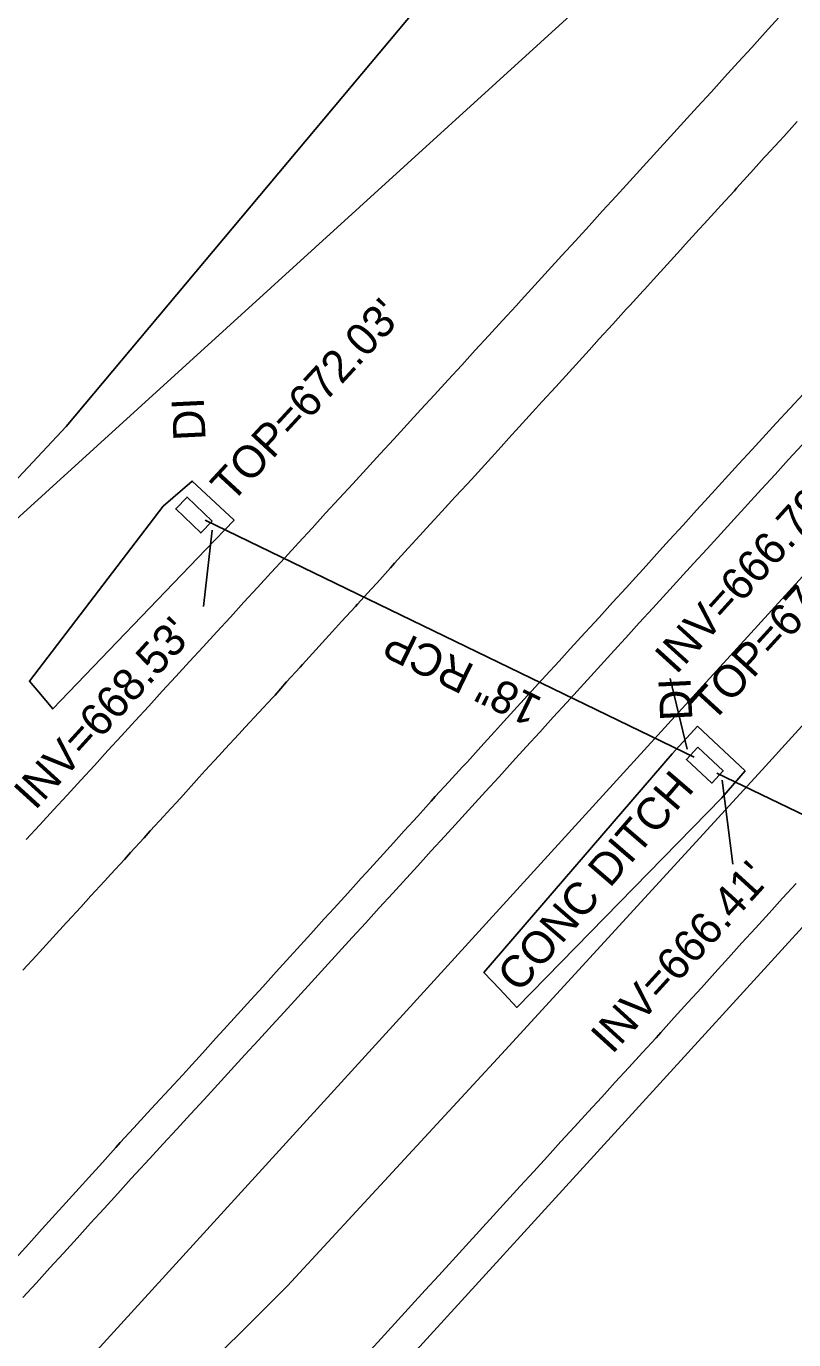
# Model space of a CAD drawing. Extents: x 1806071 to 1809844, y 912722 to 917035.
# Drawn here: x 1807955 to 1808050.3, y 914800.2 to 914963.4 of the extents above; entities that cross this region are included whole.
import ezdxf

# ---------------------------------------------------------------- set-up
doc = ezdxf.new("R2010")
doc.units = 0
for name, color, linetype in [('Exist Guardrail Cable Guide Rail', 7, 'Continuous'), ('Exist Horizontal Alignment', 7, 'Continuous'), ('Exist Roads EOP', 7, 'Continuous'), ('Exist Roads EOT', 7, 'Continuous'), ('Exist Structure Minor Drop Inlet', 7, 'Continuous'), ('Exist Structure Minor Drop Inlet Text', 7, 'Continuous'), ('Exist Structure Minor Drop Inlet Top Elevation', 7, 'Continuous'), ('Exist Structure Minor Paved Ditch or Gutter', 7, 'Continuous'), ('Exist Structure Minor Paved Ditch or Gutter Text', 7, 'Continuous'), ('Exist Structure Minor Pipes RCP 18 Inch', 7, 'Continuous'), ('Exist Structure Minor Pipes RCP 18 Inch Invert', 7, 'Continuous'), ('Exist Structure Minor Pipes RCP 18 Inch Text', 7, 'Continuous'), ('Exist Vegetation Hedge Row', 7, 'Continuous'), ('Exist Vegetation Woods Line', 7, 'Continuous')]:
    doc.layers.add(name, color=color, linetype=linetype)

msp = doc.modelspace()

# ---------------------------------------------------------------- linework, layer by layer
at = {"layer": 'Exist Guardrail Cable Guide Rail'}
msp.add_lwpolyline([(1807974.04, 914793.5), (1807987.44, 914806.88), (1808014.49, 914836.2), (1808046.81, 914871.43), (1808079.07, 914907.03), (1808115.43, 914946.85), (1808153.1, 914988.37), (1808190.68, 915029.49), (1808228.19, 915070.67), (1808264.68, 915110.73), (1808292.14, 915140.7), (1808316.64, 915167.2)], dxfattribs=at)
at = {"layer": 'Exist Horizontal Alignment'}
msp.add_line((1806073.69, 912724.84), (1809374.2, 916346.52), dxfattribs=at)
at = {"layer": 'Exist Roads EOP'}
for points in [[(1808048.45, 914964.45), (1808046.77, 914962.6), (1808045.08, 914960.75), (1808043.4, 914958.91), (1808041.72, 914957.06), (1808040.03, 914955.21), (1808038.35, 914953.36), (1808036.66, 914951.52), (1808034.98, 914949.67), (1808033.3, 914947.82), (1808031.61, 914945.97), (1808029.93, 914944.13), (1808028.24, 914942.28), (1808026.56, 914940.43), (1808024.88, 914938.58), (1808023.19, 914936.73), (1808021.51, 914934.89), (1808019.82, 914933.04), (1808018.14, 914931.19), (1808016.46, 914929.34), (1808015.83, 914928.65), (1808014.14, 914926.81), (1808012.45, 914924.97), (1808010.76, 914923.13), (1808009.07, 914921.28), (1808007.38, 914919.44), (1808005.69, 914917.6), (1808004, 914915.76), (1808002.31, 914913.91), (1808000.62, 914912.07), (1807998.93, 914910.23), (1807997.24, 914908.38), (1807995.55, 914906.54), (1807993.86, 914904.7), (1807992.17, 914902.86), (1807990.48, 914901.01), (1807988.79, 914899.17), (1807987.1, 914897.33), (1807985.41, 914895.49), (1807983.72, 914893.64), (1807982.03, 914891.8), (1807980.34, 914889.96), (1807978.65, 914888.12), (1807976.96, 914886.27), (1807975.27, 914884.43), (1807973.58, 914882.59), (1807971.89, 914880.75), (1807970.2, 914878.9), (1807968.52, 914877.06), (1807966.83, 914875.22), (1807965.14, 914873.38), (1807963.45, 914871.53), (1807961.76, 914869.69), (1807960.07, 914867.85), (1807958.38, 914866.01), (1807956.69, 914864.16), (1807955, 914862.32)], [(1807954.57, 914805.4), (1807956.26, 914807.25), (1807957.94, 914809.09), (1807959.62, 914810.94), (1807961.31, 914812.79), (1807962.99, 914814.64), (1807964.68, 914816.49), (1807966.36, 914818.34), (1807968.04, 914820.18), (1807968.62, 914820.82), (1807970.31, 914822.66), (1807972, 914824.51), (1807973.69, 914826.35), (1807975.38, 914828.19), (1807977.07, 914830.03), (1807978.77, 914831.87), (1807980.46, 914833.72), (1807982.15, 914835.56), (1807983.84, 914837.4), (1807985.53, 914839.24), (1807987.04, 914840.89), (1807988.72, 914842.74), (1807990.41, 914844.59), (1807992.09, 914846.43), (1807993.78, 914848.28), (1807995.46, 914850.13), (1807997.15, 914851.98), (1807998.83, 914853.82), (1808000.52, 914855.67), (1808002.2, 914857.52), (1808003.6, 914859.05), (1808005.28, 914860.9), (1808006.97, 914862.74), (1808008.65, 914864.59), (1808010.34, 914866.44), (1808012.02, 914868.29), (1808013.71, 914870.13), (1808015.39, 914871.98), (1808017.07, 914873.83), (1808018.76, 914875.68), (1808020.44, 914877.52), (1808022.13, 914879.37), (1808023.81, 914881.22), (1808025.5, 914883.06), (1808027.18, 914884.91), (1808028.87, 914886.76), (1808029.43, 914887.38), (1808031.12, 914889.23), (1808032.8, 914891.07), (1808034.49, 914892.92), (1808036.17, 914894.76), (1808037.86, 914896.61), (1808039.55, 914898.46), (1808041.23, 914900.3), (1808042.92, 914902.15), (1808044.6, 914903.99), (1808046.29, 914905.84), (1808047.98, 914907.69), (1808049.66, 914909.53), (1808051.35, 914911.38)], [(1808050.59, 914856.87), (1808048.91, 914855.02), (1808047.23, 914853.17), (1808045.55, 914851.32), (1808043.87, 914849.47), (1808042.19, 914847.61), (1808040.51, 914845.76), (1808038.83, 914843.91), (1808037.15, 914842.06), (1808035.47, 914840.21), (1808033.79, 914838.36), (1808033.2, 914837.7), (1808031.51, 914835.85), (1808029.82, 914834.01), (1808028.14, 914832.16), (1808026.45, 914830.31), (1808024.77, 914828.47), (1808023.08, 914826.62), (1808021.39, 914824.78), (1808019.71, 914822.93), (1808018.02, 914821.08), (1808016.34, 914819.24), (1808014.65, 914817.39), (1808012.96, 914815.55), (1808011.28, 914813.7), (1808009.59, 914811.85), (1808007.91, 914810.01), (1808006.22, 914808.16), (1808004.53, 914806.32), (1808002.85, 914804.47), (1808001.16, 914802.62), (1807999.48, 914800.78), (1807997.79, 914798.93)]]:
    msp.add_lwpolyline(points, dxfattribs=at)
at = {"layer": 'Exist Roads EOT'}
msp.add_line((1807617.6, 914375.74), (1808224.93, 915041.78), dxfattribs=at)
for points in [[(1807954.57, 914846.08), (1807956.26, 914847.93), (1807956.62, 914848.32), (1807958.31, 914850.16), (1807960.01, 914852), (1807960.08, 914852.08), (1807961.76, 914853.93), (1807963.02, 914855.31), (1807964.71, 914857.15), (1807965.48, 914858), (1807967.18, 914859.84), (1807967.96, 914860.69), (1807969.63, 914862.55), (1807970.4, 914863.39), (1807972.09, 914865.23), (1807972.46, 914865.63), (1807974.14, 914867.48), (1807974.8, 914868.2), (1807976.47, 914870.06), (1807977.22, 914870.89), (1807978.91, 914872.74), (1807979.68, 914873.59), (1807981.38, 914875.42), (1807982.17, 914876.28), (1807983.87, 914878.11), (1807985.58, 914879.94), (1807985.89, 914880.28), (1807987.32, 914881.91), (1807989, 914883.76), (1807989.28, 914884.07), (1807990.97, 914885.91), (1807991.73, 914886.75), (1807993.41, 914888.6), (1807994.16, 914889.43), (1807995.86, 914891.26), (1807996.13, 914891.56), (1807997.81, 914893.42), (1807998.55, 914894.24), (1808000.22, 914896.1), (1808000.73, 914896.68), (1808002.43, 914898.52), (1808003.43, 914899.61), (1808005.14, 914901.51), (1808006.58, 914903.08), (1808008.27, 914904.91), (1808009.08, 914905.79), (1808010.27, 914907.05), (1808011.94, 914908.9), (1808012.75, 914909.8), (1808013.97, 914911.14), (1808014.94, 914912.21), (1808016.61, 914914.06), (1808017.84, 914915.42), (1808019.05, 914916.75), (1808020.74, 914918.59), (1808022.01, 914919.96), (1808023.22, 914921.3), (1808024.9, 914923.15), (1808026.15, 914924.52), (1808027.83, 914926.37), (1808029.51, 914928.21), (1808029.93, 914928.67), (1808031.62, 914930.51), (1808031.77, 914930.68), (1808032.88, 914931.9), (1808034.57, 914933.77), (1808036.25, 914935.61), (1808036.87, 914936.29), (1808038.54, 914938.15), (1808039.16, 914938.84), (1808040.86, 914940.68), (1808041.24, 914941.09), (1808042.93, 914942.94), (1808043.21, 914943.25), (1808044.89, 914945.11), (1808044.98, 914945.21), (1808046.64, 914947.08), (1808046.82, 914947.28), (1808048.52, 914949.11), (1808049.05, 914949.69), (1808050.72, 914951.55)], [(1807953.64, 914810.24), (1807955.32, 914812.1), (1807956.99, 914813.96), (1807958.21, 914815.31), (1807959.89, 914817.16), (1807961.57, 914819), (1807962.78, 914820.34), (1807964.45, 914822.19), (1807966.12, 914824.05), (1807966.67, 914824.66), (1807968.36, 914826.5), (1807970.06, 914828.34), (1807971.05, 914829.42), (1807972.74, 914831.26), (1807974.43, 914833.1), (1807975.19, 914833.93), (1807976.87, 914835.78), (1807978.55, 914837.63), (1807979.54, 914838.72), (1807981.22, 914840.57), (1807982.9, 914842.42), (1807984.37, 914844.03), (1807986.04, 914845.88), (1807987.72, 914847.73), (1807988.64, 914848.75), (1807990.32, 914850.6), (1807992, 914852.45), (1807993.23, 914853.81), (1807994.91, 914855.66), (1807996.6, 914857.51), (1807997.25, 914858.23), (1807998.93, 914860.08), (1808000.61, 914861.93), (1808001.93, 914863.39), (1808003.6, 914865.24), (1808005.28, 914867.1), (1808005.79, 914867.66), (1808007.48, 914869.5), (1808009.17, 914871.34), (1808009.77, 914871.98), (1808011.45, 914873.84), (1808013.12, 914875.69), (1808013.87, 914876.52), (1808015.55, 914878.37), (1808017.23, 914880.22), (1808017.77, 914880.82), (1808019.46, 914882.66), (1808021.15, 914884.5), (1808022.16, 914885.61), (1808023.86, 914887.45), (1808025.55, 914889.3), (1808026.12, 914889.92), (1808027.81, 914891.76), (1808029.5, 914893.6), (1808030.29, 914894.47), (1808031.96, 914896.32), (1808033.64, 914898.18), (1808034.87, 914899.55), (1808036.55, 914901.4), (1808038.23, 914903.25), (1808039.25, 914904.38), (1808040.94, 914906.22), (1808042.63, 914908.06), (1808043.45, 914908.96), (1808045.14, 914910.8), (1808046.83, 914912.65), (1808048.12, 914914.05), (1808049.82, 914915.89), (1808051.52, 914917.72)], [(1807953.64, 914810.24), (1807955.32, 914812.1), (1807956.99, 914813.96), (1807958.21, 914815.31), (1807959.89, 914817.16), (1807961.57, 914819), (1807962.78, 914820.34), (1807964.45, 914822.19), (1807966.12, 914824.05), (1807966.67, 914824.66), (1807968.36, 914826.5), (1807970.06, 914828.34), (1807971.05, 914829.42), (1807972.74, 914831.26), (1807974.43, 914833.1), (1807975.19, 914833.93), (1807976.87, 914835.78), (1807978.55, 914837.63), (1807979.54, 914838.72), (1807981.22, 914840.57), (1807982.9, 914842.42), (1807984.37, 914844.03), (1807986.04, 914845.88), (1807987.72, 914847.73), (1807988.64, 914848.75), (1807990.32, 914850.6), (1807992, 914852.45), (1807993.23, 914853.81), (1807994.91, 914855.66), (1807996.6, 914857.51), (1807997.25, 914858.23), (1807998.93, 914860.08), (1808000.61, 914861.93), (1808001.93, 914863.39), (1808003.6, 914865.24), (1808005.28, 914867.1), (1808005.79, 914867.66), (1808007.48, 914869.5), (1808009.17, 914871.34), (1808009.77, 914871.98), (1808011.45, 914873.84), (1808013.12, 914875.69), (1808013.87, 914876.52), (1808015.55, 914878.37), (1808017.23, 914880.22), (1808017.77, 914880.82), (1808019.46, 914882.66), (1808021.15, 914884.5), (1808022.16, 914885.61), (1808023.86, 914887.45), (1808025.55, 914889.3), (1808026.12, 914889.92), (1808027.81, 914891.76), (1808029.5, 914893.6), (1808030.29, 914894.47), (1808031.96, 914896.32), (1808033.64, 914898.18), (1808034.87, 914899.55), (1808036.55, 914901.4), (1808038.23, 914903.25), (1808039.25, 914904.38), (1808040.94, 914906.22), (1808042.63, 914908.06), (1808043.45, 914908.96), (1808045.14, 914910.8), (1808046.83, 914912.65), (1808048.12, 914914.05), (1808049.82, 914915.89), (1808051.52, 914917.72)]]:
    msp.add_lwpolyline(points, dxfattribs=at)
at = {"layer": 'Exist Structure Minor Drop Inlet'}
for points in [[(1807978.08, 914901.9), (1807974.96, 914904.87), (1807973.55, 914903.4), (1807976.67, 914900.42)], [(1808038.4, 914873.79), (1808041.55, 914870.84), (1808040.12, 914869.33), (1808036.98, 914872.28)]]:
    msp.add_lwpolyline(points, close=True, dxfattribs=at)
at = {"layer": 'Exist Structure Minor Paved Ditch or Gutter'}
for p, q in [((1808035.21, 914872.99), (1808038.33, 914876.4)), ((1808038.33, 914876.4), (1808044.28, 914870.85)), ((1808044.28, 914870.85), (1808041.38, 914867.49))]:
    msp.add_line(p, q, dxfattribs=at)
for points in [[(1807971.99, 914903.75), (1807975.61, 914906.87), (1807980.81, 914901.99), (1807977.31, 914898.36)], [(1807971.99, 914903.75), (1807955.39, 914881.99), (1807956.55, 914880.62), (1807958.28, 914878.56), (1807977.31, 914898.36)], [(1808035.21, 914872.99), (1808011.83, 914845.8), (1808013.79, 914843.72), (1808015.91, 914841.46), (1808041.38, 914867.49)]]:
    msp.add_lwpolyline(points, dxfattribs=at)
at = {"layer": 'Exist Structure Minor Pipes RCP 18 Inch'}
for p, q in [((1808037.94, 914872.55), (1807977.21, 914902.01)), ((1808040.77, 914870.56), (1808130.73, 914827.05))]:
    msp.add_line(p, q, dxfattribs=at)
at = {"layer": 'Exist Structure Minor Pipes RCP 18 Inch Invert'}
for p, q in [((1807978.1, 914900.76), (1807977.01, 914891.29)), ((1808037.07, 914873.55), (1808034.94, 914882.35)), ((1808041.42, 914869.68), (1808042.75, 914859.24))]:
    msp.add_line(p, q, dxfattribs=at)
at = {"layer": 'Exist Vegetation Hedge Row'}
msp.add_lwpolyline([(1808182.81, 915194.98), (1808219.38, 915225.05), (1808257.17, 915255.38), (1808289.14, 915283.6), (1808381.78, 915355.26), (1808385.36, 915351.44), (1808204.93, 915154.1), (1808068.87, 915006.91), (1807946.32, 914895.38)], dxfattribs=at)
at = {"layer": 'Exist Vegetation Woods Line'}
msp.add_lwpolyline([(1808182.81, 915194.98), (1808194.59, 915182.96), (1808123.23, 915089.31), (1808048.18, 915019.02), (1807959.95, 914913.66), (1807901.26, 914850.85), (1807887.11, 914855.83), (1807879.29, 914881.53), (1807880.44, 914923.49), (1807894.04, 914955.02), (1807915.84, 914974.97), (1807953.6, 915004.2), (1807991.45, 915032.47), (1808031.33, 915065.58), (1808068.31, 915096.93), (1808108.92, 915131.55), (1808145.7, 915163.42), (1808182.81, 915194.98)], dxfattribs=at)

# ---------------------------------------------------------------- texts
at = {"layer": 'Exist Structure Minor Drop Inlet Text'}
for p in [(1807977.28, 914911.99), (1808037.73, 914877.18)]:
    msp.add_text('DI', height=4, rotation=92.8422, dxfattribs=at).set_placement(p)
at = {"layer": 'Exist Structure Minor Drop Inlet Top Elevation'}
for s, rotation, p in [("TOP=672.03'", 47.3058, (1807980.52, 914904.03)), ("TOP=672.33'", 47.6013, (1808040.22, 914876.75))]:
    msp.add_text(s, height=4, rotation=rotation, dxfattribs=at).set_placement(p)
at = {"layer": 'Exist Structure Minor Paved Ditch or Gutter Text'}
msp.add_text('CONC DITCH', height=4, rotation=49.3028, dxfattribs=at).set_placement((1808016.22, 914843.14))
at = {"layer": 'Exist Structure Minor Pipes RCP 18 Inch Invert'}
for s, rotation, p in [("INV=666.79'", 47.8244, (1808035.7, 914882.72)), ("INV=668.53'", 47.7197, (1807956.09, 914865.85)), ("INV=666.41'", 47.7178, (1808027.74, 914835.53))]:
    msp.add_text(s, height=4, rotation=rotation, dxfattribs=at).set_placement(p)
at = {"layer": 'Exist Structure Minor Pipes RCP 18 Inch Text'}
msp.add_text('18" RCP', height=4, rotation=154.1204, dxfattribs=at).set_placement((1808019.25, 914879.82))

doc.saveas('drawing.dxf')
